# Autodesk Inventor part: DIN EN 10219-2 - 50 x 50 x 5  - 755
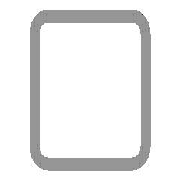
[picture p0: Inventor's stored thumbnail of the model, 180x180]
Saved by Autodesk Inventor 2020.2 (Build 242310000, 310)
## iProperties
IsCustomPart: 1
_CCFamilyMember: 16
_CCFamilyDisplayName: DIN EN 10219-2 (Quadratisches Hohlprofil - Kaltgeformt) - Kaltgeformte, geschweißte Baustahl-Hohlprofile aus unlegiertem Feinkorn-Baustahl
_FrameMemberDoc: Frame Member File
_Version: 15.0.0
_GetPNFromCC: 1
Created: 2019-01
Part Number: DIN EN 10219-2 - 50 x 50 x 5  - 755
Material: Stahl, weich
Description: Kaltgeformte, geschweißte Baustahl-Hohlprofile aus unlegiertem Feinkorn-Baustahl
Document SubType Name: Modeling
Standard: DIN
Designer: lutzd
Standard Revision: 2006-07
Standards Organization: DIN
Language: de-DE
Size Designation: 50 x 50 x 5
Categories: <MemberInstance><Categories><Category DisplayName="Profile" InternalName="089c4875-fa83-4c05-b084-43b9cc11f5ed" Mnemonic="GRDR"><CategoryParameter DisplayName="
Stock Number: 50 x 50 x 5
Mass: 4952.51 g
Surface Area: 2540.28 cm^2
Volume: 630.893 cm^3
Density: 7.85 g/cm^3
Appearance: Semi-Polished(8)
G_L: 755,000 mm
G_W: 50,000 mm
G_H: 50,000 mm
+E28346AA-8DB2-4470-8536-A7F610C54E7C+SCHNITTDETAIL1: Schnittwinkel 90,00 grd
+FF1EA4DA-75D5-43BB-8F31-6BE8159C8E85+SCHNITTDETAIL2: Schnittwinkel 90,00 grd
DocNumber: ADSK-014434
Folder: .
Mass: 4,953 kg
VLT_Material: Stahl, weich
Dimensions: 50x50x755 mm
Title: Profil-Bauteil
Author: lutzd
Revision Number: -
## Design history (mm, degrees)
node "Startebene"
node "Endebene"
sketch "Skizze"
  geometry: L1 (-25, -15)-(-25, 15); L2 (-15, 25)-(15, 25); L3 (25, 15)-(25, -15); L4 (15, -25)-(-15, -25); L5 (-15, 20)-(15, 20); L6 (20, 15)-(20, -15); L7 (15, -20)-(-15, -20); L8 (-20, -15)-(-20, 15); L9 (0, 37.899)-(0, -37.899) reference; L10 (-37.899, 0)-(37.899, 0) reference; A1 r 10 centre (-15, -15) between (-25, -15) and (-15, -25); A2 r 10 centre (-15, 15) between (-15, 25) and (-25, 15); A3 r 10 centre (15, 15) between (25, 15) and (15, 25); A4 r 10 centre (15, -15) between (15, -25) and (25, -15); A5 r 5 centre (-15, 15) between (-15, 20) and (-20, 15); A6 r 5 centre (15, 15) between (20, 15) and (15, 20); A7 r 5 centre (15, -15) between (15, -20) and (20, -15); A8 r 5 centre (-15, -15) between (-20, -15) and (-15, -20)
  constraints: 16 end point, 16 point on circle, 8 centre point, 8 tangent, 4 parallel, 3 equal radius, 2 perpendicular, 7 other
  dimensions: "d7" = 10 radius of A1 (= G_IR); "d10" = 50 distance between parallel lines of L2 L4 (= G_H); "d11" = 50 distance between parallel lines of L1 L3 (= G_W); "d12" = 5 distance between parallel lines of L3 L6 (= G_T); "d15" = 25 distance between parallel lines of L2 L10 (= 0.5 x d10); "d16" = 25 distance between parallel lines of L9 L3 (= 0.5 x d11)
extrude "Körper" new body sketch "Skizze" stored distance "d3" = 755 (= G_L); taper "d4" = 0 deg
node "Driven Length"
  sketch "Sketch3"
    geometry: L1 (0, 0)-(10, 0) reference
    constraints: 2 end point, 1 horizontal
  workplane "Work Plane3"
  sketch "Sketch4"
    geometry: L1 (-2, 25)-(12, 25) reference; L2 (-2, 780)-(12, 780) reference
    dimensions: "d18" = 755 distance between parallel lines of L1 L2 (derived)
workplane "Arbeitsebene4"
feature "Trennen1"
workplane "Arbeitsebene5"
feature "Trennen2"
body "Solid1"
other parameters: "G_W" = 50 [user parameter; used in 1 equation term], "G_H" = 50 [user parameter; used in 1 equation term], "G_T" = 5 [user parameter; used in 1 equation term], "G_IR" = 10 [user parameter; used in 1 equation term], "G_L" = 755 (= d18) [user parameter; used in 1 equation term], "G_OFFSET_START" = -25 [user parameter; used in 1 equation term], "G_OFFSET_END" = -25 [user parameter; used in 1 equation term], "d13" = 25 (= -G_OFFSET_START), "B_L" = 805 [user parameter; used in 1 equation term], "d17" = 90 deg
